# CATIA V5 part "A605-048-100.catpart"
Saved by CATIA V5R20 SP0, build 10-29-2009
Part number: A605-048-100
Source: Unknown
Property "A": "0.000"
Property "ARTICLENO": "A605-048-100"
Property "BOMINFO": "A605-048-100"
Property "CODE": "A605-048-100"
Property "D": "9.000"
Property "FORM": "A"
Property "L": "100.000"
Property "L1": "70.000"
Property "LINA": "A605-048-100"
Property "NB": "A605-048-100"
Property "NBSYN": "$CODE."
Property "NN": "A605"
Property "NT": "Wear Plates, self-lubricating"
Property "SCREW": "2*M8X16"
Property "SUPPLIER": "CF"
Property "W": "48.000"
Bounding box of the stored display mesh (mm): x -48 to 0, y 0 to 5, z -100 to 0
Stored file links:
  C:\Users\Utente\Desktop\3D files A605\A605-048-100.catpart
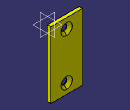
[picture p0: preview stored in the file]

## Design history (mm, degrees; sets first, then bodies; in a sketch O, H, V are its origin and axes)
Body1 "Geometry.1" (main body)
  Solid1 "A605-048-100.catpart": solid without history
